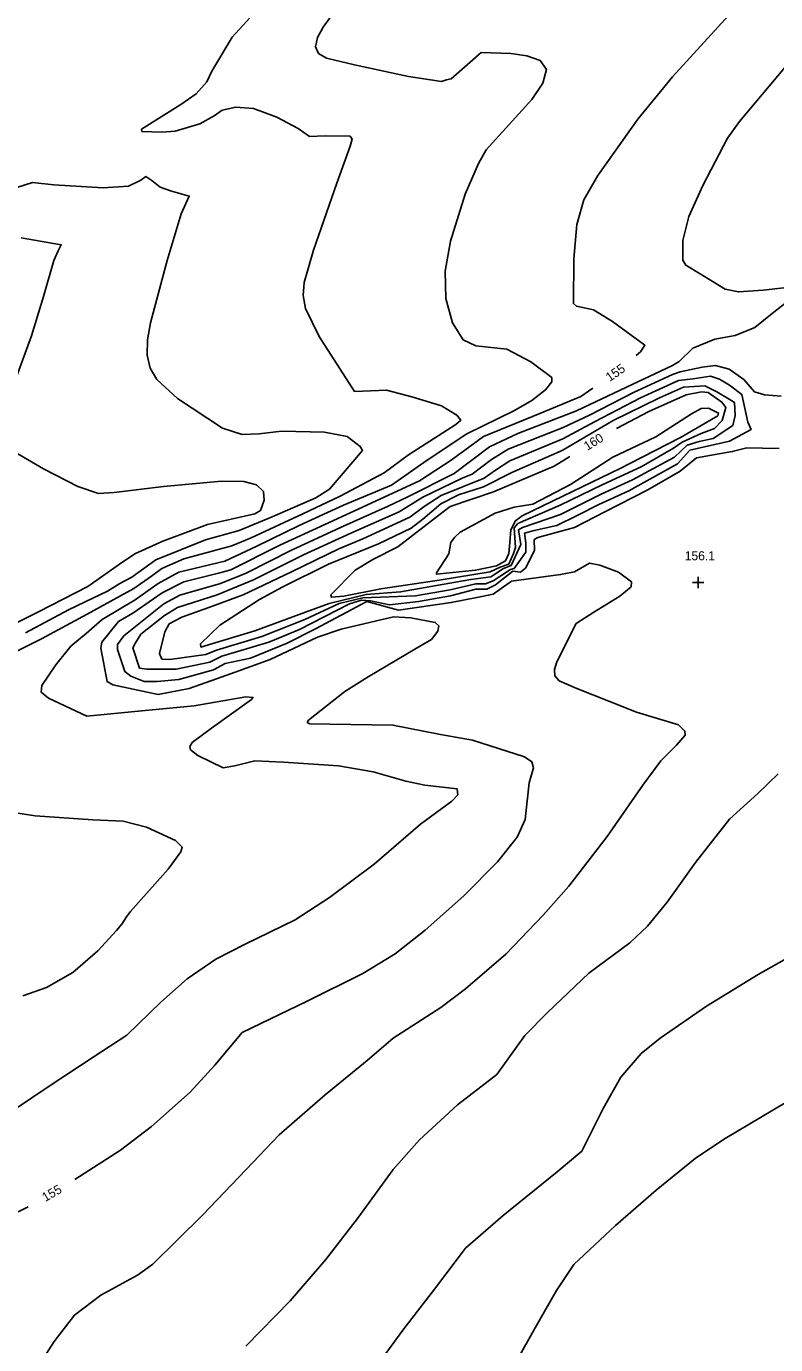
# Model space of a CAD drawing. Extents: x 1467615 to 2003689, y 770235 to 1108726.
# Drawn here: x 2002701.4 to 2002867.2, y 771281.4 to 771573 of the extents above; entities that cross this region are included whole.
import ezdxf

# ---------------------------------------------------------------- set-up
doc = ezdxf.new("R2010")
doc.units = 0
for name, color, linetype in [('RD_DTM_Major1', 7, 'Continuous'), ('RD_DTM_Major1_Lbl', 7, 'Continuous'), ('RD_DTM_Minor1', 7, 'Continuous'), ('RD_DTM_Spot_Elev', 7, 'Continuous')]:
    doc.layers.add(name, color=color, linetype=linetype)

msp = doc.modelspace()

# ---------------------------------------------------------------- linework, layer by layer
at = {"layer": 'RD_DTM_Major1'}
for points in [[(2002858.41, 771577.24), (2002854.46, 771572.83), (2002844.32, 771561.79), (2002836.69, 771552.46), (2002827.85, 771539.96), (2002824.7, 771534.57), (2002823.21, 771529.15), (2002822.52, 771521.56), (2002822.42, 771511.65), (2002823.08, 771511.08), (2002826.86, 771510.27), (2002831.04, 771507.66), (2002838.24, 771502.43), (2002837.3, 771501.01), (2002836.32, 771500.2)], [(2002826.74, 771492.94), (2002824.08, 771491.1), (2002814.96, 771487.36), (2002802.54, 771482.27), (2002795.36, 771477), (2002788.38, 771472.45), (2002777.69, 771467.49), (2002767.46, 771462.77), (2002757.48, 771458.25), (2002746.66, 771452.74), (2002744.17, 771452.07), (2002736.22, 771450.11), (2002731.45, 771447.69), (2002724.97, 771443.19), (2002721.82, 771441.35), (2002718.12, 771436.78), (2002717.91, 771435.41), (2002719.25, 771428.05), (2002720.57, 771427.34), (2002730.58, 771425.23), (2002737.45, 771426.56), (2002743.47, 771428.7), (2002747.56, 771430.13), (2002755.37, 771432.95), (2002765.8, 771437.91), (2002771.05, 771439.66), (2002782.61, 771442.34), (2002786.44, 771442.18), (2002791.86, 771441.14), (2002792.64, 771440.35), (2002792.42, 771439.24), (2002791, 771437.37), (2002787.37, 771435.19), (2002777.04, 771429.1), (2002771.87, 771425.87), (2002763.83, 771419.52), (2002763.56, 771419.01), (2002764.14, 771418.73), (2002768.51, 771418.62), (2002782.48, 771418.42), (2002793.03, 771416.38), (2002800.13, 771415.07), (2002811.63, 771411.42), (2002813.21, 771410.33), (2002813.56, 771409), (2002812.63, 771405.68), (2002811.78, 771397.52), (2002810.01, 771393.63), (2002805.62, 771388.19), (2002798.16, 771380.68), (2002789.65, 771373.08), (2002783, 771367.82), (2002775.85, 771363.48), (2002763.5, 771357.37), (2002749.16, 771350.44), (2002743.12, 771343.21), (2002737.65, 771337.28), (2002729.07, 771329.64), (2002722.2, 771324.44), (2002712.15, 771317.96)], [(2002821.65, 771477.87), (2002818.15, 771475.71), (2002810.48, 771472.46), (2002804.73, 771470.05), (2002795.16, 771466.81), (2002792.67, 771464.87), (2002783.55, 771457.82), (2002778.02, 771455.03), (2002774.12, 771452.73), (2002768.77, 771447.23), (2002768.89, 771446.71), (2002771.67, 771446.96), (2002779.83, 771448.56), (2002792.7, 771450.47), (2002804.01, 771452.36), (2002806.21, 771453.33), (2002808.11, 771454), (2002809.16, 771456.41), (2002809.64, 771457.71), (2002809.3, 771462.07), (2002810.13, 771463.03), (2002819.5, 771467.04), (2002828.9, 771471.66), (2002837.38, 771475.57), (2002844.59, 771479.64), (2002846.47, 771480.97), (2002850.69, 771482.9), (2002853.61, 771484.05), (2002855.33, 771485.8), (2002856.18, 771488.64), (2002855.27, 771489.88), (2002852.23, 771491.97), (2002850.73, 771492.12), (2002847.4, 771491.49), (2002839.11, 771487.77), (2002831.97, 771484.01)], [(2002701.79, 771311.91), (2002688.67, 771305.46), (2002682.38, 771299.38), (2002677.41, 771294.14), (2002675.66, 771292.26), (2002674.77, 771292.05), (2002672.81, 771293.42), (2002666.87, 771300.71), (2002663.39, 771302.65), (2002661.87, 771302.69), (2002660.77, 771301.76), (2002660.09, 771300.08), (2002659.67, 771295.82), (2002660.45, 771290.53), (2002664.03, 771279.15)]]:
    msp.add_lwpolyline(points, dxfattribs=at)
at = {"layer": 'RD_DTM_Minor1'}
for points in [[(2002753.26, 771577.51), (2002746.95, 771570.55), (2002742.41, 771563.05), (2002741.36, 771560.71), (2002738.94, 771558.01), (2002735.59, 771555.7), (2002726.89, 771550.21), (2002726.95, 771549.71), (2002731.39, 771549.53), (2002734.29, 771549.78), (2002739.81, 771551.41), (2002742.97, 771553.2), (2002744.69, 771554.42), (2002747.72, 771555.07), (2002751.68, 771554.8), (2002756.83, 771552.9), (2002761.54, 771550.37), (2002764.06, 771548.62), (2002767.48, 771548.73), (2002773.03, 771548.69), (2002773.51, 771548.04), (2002773.02, 771546.47), (2002770.08, 771538.27), (2002764.91, 771523.45), (2002762.83, 771516.32), (2002762.64, 771513.45), (2002763.16, 771510.6), (2002766.18, 771504.36), (2002774.01, 771492.18), (2002781.1, 771492.47), (2002786.69, 771491.03), (2002793.25, 771489.03), (2002796.6, 771487.01), (2002797.53, 771485.89), (2002796.4, 771484.94), (2002785.93, 771478.18), (2002780.59, 771474.19), (2002770.82, 771469.07), (2002762.6, 771465.16), (2002751.15, 771459.83), (2002746.85, 771458.11), (2002736.26, 771455.18), (2002731.39, 771453.07), (2002729.1, 771451.34), (2002725.17, 771448.64), (2002714.89, 771443), (2002704.77, 771437.49), (2002693.32, 771431.86)], [(2002770.12, 771576.95), (2002767.07, 771572.8), (2002765.82, 771570.48), (2002765.37, 771568.46), (2002766.06, 771566.99), (2002767.83, 771565.96), (2002773.98, 771564.44), (2002785.97, 771561.88), (2002793.27, 771560.75), (2002794.33, 771561.11), (2002795.4, 771561.37), (2002797.77, 771563.42), (2002801.99, 771567.16), (2002808.55, 771566.95), (2002812.12, 771566.48), (2002815.07, 771565.4), (2002816.46, 771563.42), (2002815.64, 771560.39), (2002813.19, 771556.76), (2002803.13, 771545.64), (2002801.4, 771542.66), (2002798.5, 771535.84), (2002795.21, 771525.48), (2002794.08, 771518.84), (2002794.22, 771512.79), (2002795.66, 771507.41), (2002798.03, 771503.67), (2002800.83, 771502.34), (2002807.68, 771501.57), (2002812.97, 771498.77), (2002817.63, 771495.3), (2002817.66, 771494.35), (2002816.25, 771492.61), (2002813.24, 771490.24), (2002809.28, 771487.97), (2002798.88, 771482.82), (2002790.05, 771477.04), (2002782.2, 771471.48), (2002771.57, 771467.06), (2002761.78, 771462.54), (2002752.36, 771458.02), (2002745.32, 771454.71), (2002735.16, 771452.23), (2002730.54, 771449.74), (2002725.49, 771446.13), (2002718.14, 771441.81), (2002714.66, 771438.66), (2002711.25, 771435.87), (2002707.89, 771431.77), (2002704.81, 771427.19), (2002704.71, 771425.7), (2002706.3, 771424.42), (2002714.75, 771420.43), (2002726.92, 771421.57), (2002738.5, 771422.67), (2002749.98, 771424.69), (2002751.54, 771424.57), (2002751.18, 771424.08), (2002742.34, 771417.74), (2002738.11, 771414.56), (2002737.55, 771413.7), (2002737.68, 771412.97), (2002739.36, 771411.74), (2002744.92, 771408.96), (2002747.52, 771409.45), (2002751.96, 771410.51), (2002758.27, 771410.27), (2002770.47, 771409.42), (2002778.14, 771408.07), (2002785.32, 771406.05), (2002789.57, 771405.14), (2002796.68, 771404.32), (2002796.87, 771403.03), (2002795.55, 771401.6), (2002788.57, 771396.54), (2002778.31, 771387.66), (2002768.45, 771380.29), (2002760.87, 771375.39), (2002749.63, 771369.93), (2002743.35, 771366.63), (2002736.99, 771362.35), (2002731.14, 771357.15), (2002723.66, 771349.86), (2002716.19, 771345.01), (2002706.92, 771338.85), (2002693.99, 771330.22)], [(2002869.22, 771563.86), (2002859.14, 771551.94), (2002856.48, 771548.27), (2002851.05, 771537.78), (2002847.99, 771530.89), (2002846.61, 771525.58), (2002846.62, 771521.27), (2002847.32, 771520.13), (2002850.49, 771518.23), (2002856.03, 771514.83), (2002858.93, 771514.22), (2002864.38, 771514.65), (2002874.2, 771515.72)], [(2002697.45, 771536.75), (2002702.75, 771538.4), (2002707.51, 771537.89), (2002718.4, 771537.22), (2002724.02, 771537.63), (2002726.75, 771538.91), (2002727.87, 771539.73), (2002729.18, 771538.88), (2002731.02, 771537.42), (2002733.26, 771536.59), (2002737.45, 771535.42), (2002735.62, 771531.48), (2002732.54, 771521.16), (2002728.89, 771507.43), (2002728.23, 771503.63), (2002728.14, 771500.28), (2002728.78, 771497.36), (2002730.25, 771494.84), (2002734.86, 771490.66), (2002744.76, 771484.08), (2002749.14, 771482.73), (2002752.93, 771482.85), (2002757.87, 771483.44), (2002767.34, 771483.18), (2002772.37, 771482.27), (2002775.26, 771480.05), (2002775.76, 771479.14), (2002768.45, 771470.59), (2002765.47, 771468.67), (2002755.75, 771464.46), (2002748.45, 771461.48), (2002741.06, 771459.37), (2002730.04, 771454.96), (2002724.76, 771451.18), (2002722.08, 771449.77), (2002719.32, 771448.02), (2002716.11, 771446.52), (2002710.76, 771443.92), (2002701.22, 771438.8)], [(2002700.23, 771526.21), (2002709.14, 771524.67), (2002708.47, 771523.35), (2002707.46, 771521.19), (2002705.19, 771513.22), (2002702.57, 771504.5), (2002696.99, 771489.41)], [(2002872.57, 771514.33), (2002866.4, 771509.44), (2002862.54, 771506.39), (2002858.22, 771504.63), (2002853.74, 771503.77), (2002848.86, 771501.76), (2002845.81, 771498.81), (2002844.38, 771497.94), (2002834.17, 771493.2), (2002823.13, 771487.97), (2002810.13, 771482.92), (2002803.85, 771480), (2002796.06, 771474.06), (2002785.83, 771468.94), (2002781.45, 771466.83), (2002770.91, 771462.13), (2002760.06, 771457.15), (2002750.04, 771452.05), (2002744.35, 771449.77), (2002735.32, 771447.15), (2002731.83, 771445.25), (2002722.97, 771438.18), (2002721.56, 771436.28), (2002721.57, 771435.14), (2002723.21, 771430.25), (2002724.5, 771429.25), (2002727.49, 771428.04), (2002730.34, 771428.1), (2002735.14, 771428.48), (2002742.79, 771430.63), (2002745.36, 771432.06), (2002750.98, 771433.23), (2002759.11, 771436.54), (2002765.34, 771439.74), (2002776.69, 771445.74), (2002783.72, 771443.84), (2002795.41, 771445.52), (2002801.07, 771446.66), (2002804.7, 771447.37), (2002808.75, 771450.27), (2002819.58, 771451.71), (2002822.69, 771452.3), (2002826.02, 771454.26), (2002828.29, 771453.82), (2002832.4, 771452.27), (2002835.29, 771450.1), (2002835.2, 771449.01), (2002832.72, 771446.91), (2002826.92, 771443.44), (2002823.06, 771440.87), (2002818.75, 771432.39), (2002818.24, 771430.72), (2002818.32, 771429.34), (2002819.28, 771428.25), (2002823.15, 771426.55), (2002830.26, 771423.71), (2002836.38, 771421.29), (2002845.67, 771418.5), (2002847.11, 771417.1), (2002847.13, 771416.23), (2002845.23, 771414.03), (2002841.73, 771410.5), (2002837.8, 771405.17), (2002829.88, 771393.8), (2002821.41, 771382.83), (2002815.77, 771376.37), (2002807.45, 771367.77), (2002798.56, 771360.08), (2002793.1, 771355.97), (2002782.52, 771349.19), (2002776.83, 771344.26), (2002767.49, 771336.67), (2002757.3, 771327.81), (2002750.05, 771320.13), (2002740.38, 771310.03), (2002729.35, 771299.19), (2002725.99, 771296.76), (2002717.86, 771292.37), (2002712.07, 771287.95), (2002707.56, 771282.14), (2002701.69, 771272.86)], [(2002868.4, 771491.15), (2002864.72, 771491.47), (2002862.48, 771492.14), (2002860.15, 771494.88), (2002856.86, 771497.17), (2002853.86, 771497.96), (2002850.89, 771497.58), (2002846.03, 771496.55), (2002844.31, 771495.98), (2002835.73, 771492), (2002825.95, 771486.96), (2002820.14, 771484.26), (2002807.99, 771479.42), (2002804.33, 771477.2), (2002800.02, 771473.95), (2002797.8, 771473.04), (2002789.1, 771468.86), (2002783.86, 771465.61), (2002773.19, 771460.91), (2002762.72, 771456.08), (2002751.68, 771450.54), (2002743.58, 771447.26), (2002734.86, 771444.41), (2002732, 771442.67), (2002726.7, 771438.54), (2002725.56, 771436.61), (2002724.98, 771435.52), (2002726.46, 771431.02), (2002728.04, 771430.82), (2002734.57, 771430.83), (2002741.99, 771432.36), (2002744.68, 771433.66), (2002755.07, 771436.78), (2002761.86, 771439.59), (2002772.86, 771445.27), (2002775.51, 771446.04), (2002777.53, 771445.89), (2002781.75, 771445.04), (2002788.18, 771445.76), (2002795.24, 771447.01), (2002800.82, 771448.46), (2002803.26, 771448.51), (2002805.19, 771449.48), (2002809.05, 771452.48), (2002810.7, 771452.25), (2002811.82, 771453.17), (2002813.82, 771457.03), (2002813.76, 771459.46), (2002814.55, 771459.95), (2002822.64, 771462.14), (2002829.35, 771465.61), (2002838.86, 771470.45), (2002846.01, 771474.59), (2002849.66, 771477.57), (2002857.56, 771478.91), (2002860.79, 771479.72), (2002864.23, 771479.66), (2002867.97, 771479.6)], [(2002854.75, 771494.92), (2002852.74, 771495.58), (2002848.89, 771495.01), (2002845.7, 771494.65), (2002837.3, 771490.81), (2002827.08, 771485.49), (2002820.06, 771481.71), (2002808.38, 771476.86), (2002805.19, 771474.79), (2002802.7, 771473.01), (2002793.16, 771469.24), (2002789.4, 771466.77), (2002786.27, 771464.39), (2002775.85, 771459.62), (2002770.54, 771457.38), (2002760.06, 771452.36), (2002749.4, 771447.27), (2002741.78, 771444.44), (2002735.82, 771442.3), (2002732.98, 771440.82), (2002732.01, 771439.08), (2002730.89, 771434.25), (2002731.38, 771433.03), (2002733.15, 771432.97), (2002741.14, 771434.05), (2002743.5, 771435), (2002753.5, 771438.03), (2002762.98, 771441.79), (2002770.64, 771445.29), (2002775.86, 771446.58), (2002787.5, 771447.03), (2002795.19, 771448.36), (2002800.82, 771449.68), (2002803.01, 771449.66), (2002804.64, 771450.37), (2002808.52, 771452.87), (2002809.31, 771453.05), (2002811.87, 771456.71), (2002811.92, 771458.73), (2002811.57, 771460.87), (2002813.72, 771461.46), (2002818.76, 771462.57), (2002823.24, 771464.79), (2002828.05, 771467.22), (2002834.65, 771470.25), (2002845.43, 771476.24), (2002848.2, 771479.26), (2002856.99, 771481.26), (2002861.72, 771483.84), (2002861.02, 771485.45), (2002859.66, 771491.55), (2002856.95, 771493.59), (2002854.75, 771494.92)], [(2002856.87, 771490.55), (2002854.15, 771492.11), (2002851.5, 771493.45), (2002846.79, 771493.14), (2002841.45, 771490.83), (2002831.25, 771485.79), (2002819.97, 771479.15), (2002808.79, 771474.31), (2002802.55, 771471.16), (2002797.01, 771469.35), (2002793.09, 771467.37), (2002789.1, 771463.95), (2002786.5, 771462), (2002779.3, 771458.49), (2002768.27, 771454.05), (2002758.14, 771449.01), (2002752.98, 771446.21), (2002744.17, 771440.54), (2002739.92, 771436.4), (2002740.03, 771435.7), (2002741.69, 771436.18), (2002751.93, 771439.29), (2002763.17, 771443.41), (2002768.41, 771445.32), (2002776.58, 771447.31), (2002784.19, 771447.89), (2002796.34, 771450.06), (2002799.76, 771450.66), (2002804.16, 771451.25), (2002806.94, 771453.04), (2002808.64, 771453.7), (2002810.76, 771458.37), (2002810.26, 771461.62), (2002811.15, 771462.11), (2002819.54, 771464.98), (2002828.53, 771469.52), (2002835.52, 771472.67), (2002844.78, 771477.69), (2002847.61, 771480.32), (2002850.28, 771481.18), (2002853.37, 771481.84), (2002857.66, 771484.7), (2002858.22, 771486.9), (2002858.04, 771489.8), (2002856.87, 771490.55)], [(2002834.94, 771476.31), (2002846.1, 771482.07), (2002854.37, 771486.86), (2002854.54, 771487.45), (2002852.3, 771488.5), (2002850.69, 771488.45), (2002848.53, 771487.29), (2002840.63, 771482.16), (2002831.13, 771477.72), (2002821.75, 771471.64), (2002813.45, 771467.26), (2002809.33, 771466.65), (2002805.14, 771465.3), (2002797.35, 771461.1), (2002796.09, 771459.9), (2002795.28, 771458.84), (2002794.84, 771456.34), (2002792.17, 771452.14), (2002792.16, 771451.79), (2002800.77, 771452.68), (2002805.39, 771453.66), (2002807.43, 771454.76), (2002808.12, 771456.41), (2002808.38, 771458.8), (2002808.6, 771461.63), (2002809.62, 771463.61), (2002811.1, 771464.69), (2002820.05, 771469.09), (2002832.89, 771475.29), (2002834.94, 771476.31)], [(2002695.96, 771480.49), (2002705.23, 771475.12), (2002712.79, 771471.21), (2002717.33, 771469.66), (2002720.8, 771469.86), (2002731.76, 771471.17), (2002744.55, 771472.37), (2002749.54, 771472.28), (2002752.34, 771471.59), (2002753.84, 771470.11), (2002754.04, 771468.16), (2002753.19, 771465.87), (2002751.94, 771465.13), (2002741.5, 771462.81), (2002731.63, 771459.14), (2002725.54, 771456.39), (2002722.75, 771454.55), (2002714.99, 771449.08), (2002704.12, 771443.51), (2002693.75, 771438.41)], [(2002867.74, 771407.69), (2002863.22, 771403.3), (2002856.95, 771397.61), (2002849.45, 771388.01), (2002843.13, 771379.27), (2002838.8, 771373.98), (2002834.9, 771370.25), (2002825.85, 771363.6), (2002816.7, 771354.89), (2002811.7, 771349.75), (2002805.47, 771341.19), (2002796.76, 771334.48), (2002788.4, 771326.72), (2002782.55, 771320.14), (2002774.88, 771309.6), (2002767.68, 771300.24), (2002759.77, 771291.08), (2002749.92, 771281.08)], [(2002696.64, 771399.43), (2002703.37, 771398.38), (2002716.14, 771397.48), (2002722.85, 771397.18), (2002727.98, 771395.88), (2002734.41, 771392.9), (2002735.89, 771391.4), (2002735.57, 771390.37), (2002732.74, 771386.6), (2002724.43, 771377.18), (2002723.52, 771376.05), (2002722.51, 771374.37), (2002721.35, 771372.97)], [(2002721.35, 771372.97), (2002717.23, 771368.53), (2002711.67, 771363.72), (2002705.88, 771360.43), (2002700.6, 771358.58)], [(2002874.16, 771369.36), (2002863.31, 771363.25), (2002851.84, 771356.27), (2002841.59, 771349.17), (2002837.42, 771345.77), (2002832.94, 771340.57), (2002829, 771333.65), (2002824.32, 771324.17), (2002818.83, 771319.62), (2002806.87, 771309.95), (2002798.57, 771302.72), (2002791.7, 771293.71), (2002784.67, 771284.62), (2002777.17, 771274.33)], [(2002869.61, 771335.11), (2002855.6, 771326.8), (2002849.39, 771322.6), (2002840.76, 771315.55), (2002831.77, 771307.79), (2002822.54, 771299.12), (2002818.66, 771293.41), (2002813.97, 771285.15), (2002805.78, 771270.5)]]:
    msp.add_lwpolyline(points, dxfattribs=at)
at = {"layer": 'RD_DTM_Spot_Elev'}
for p, q in [((2002848.75, 771450), (2002851.25, 771450)), ((2002850, 771448.75), (2002850, 771451.25))]:
    msp.add_line(p, q, dxfattribs=at)

# ---------------------------------------------------------------- texts
at = {"layer": 'RD_DTM_Major1_Lbl'}
for s, rotation, p in [('155', 34.7364, (2002830.44, 771494.29)), ('160', 31.58, (2002825.5, 771479.06)), ('155', 30.281, (2002705.6, 771312.94))]:
    msp.add_text(s, height=2, rotation=rotation, dxfattribs=at).set_placement(p)
at = {"layer": 'RD_DTM_Spot_Elev'}
msp.add_text('156.1', height=2, dxfattribs=at).set_placement((2002847.05, 771454.88))

doc.saveas('drawing.dxf')
